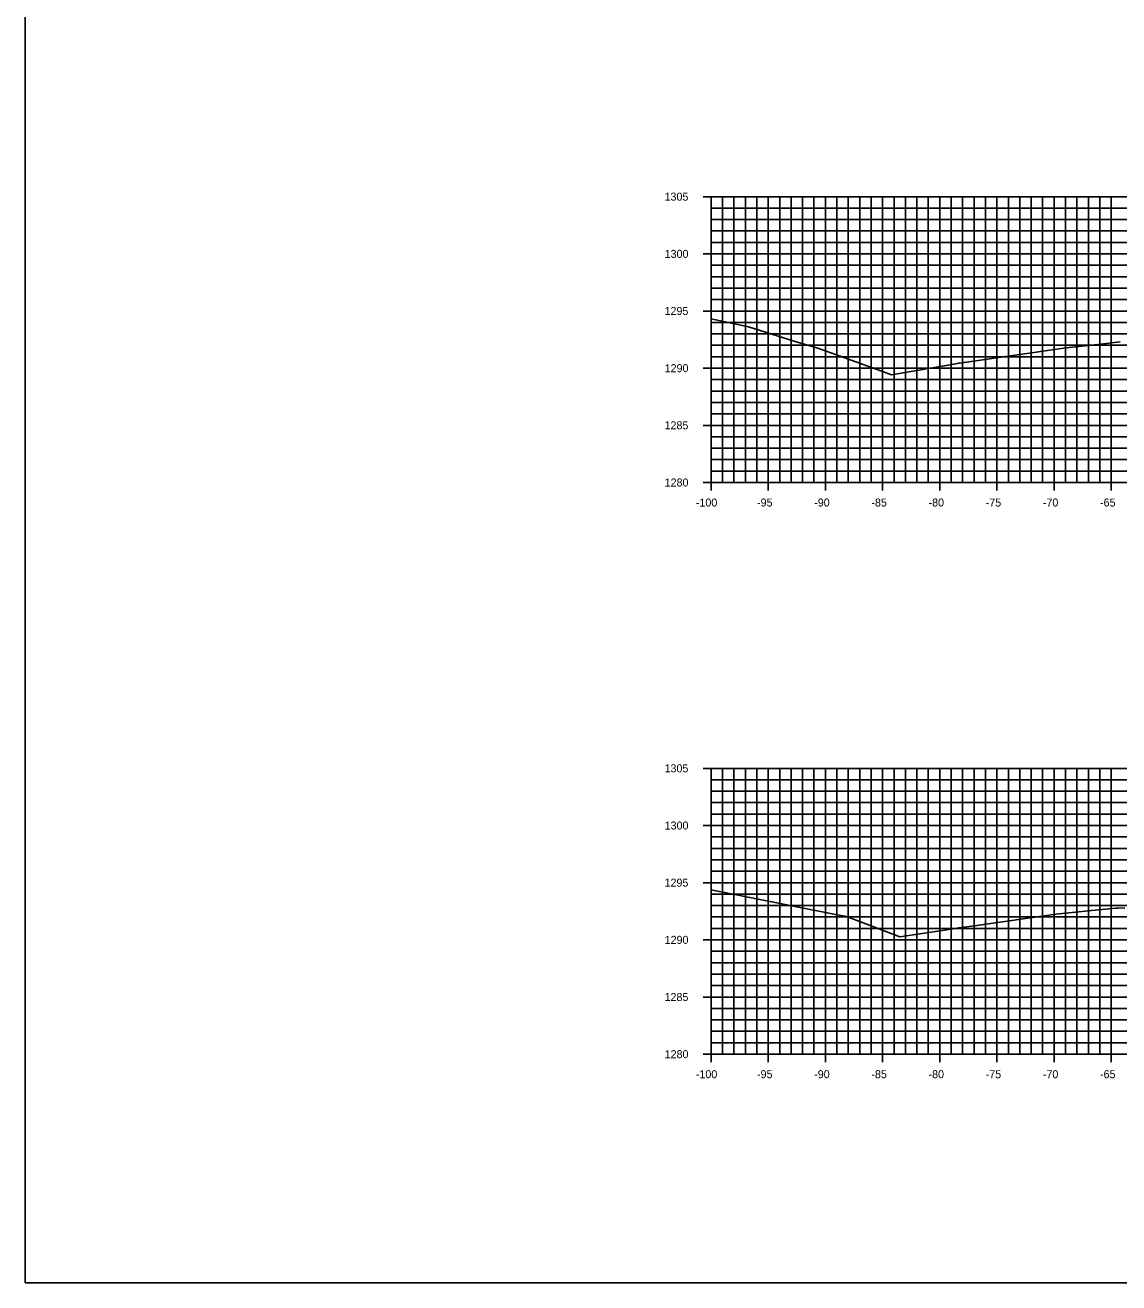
# Model space of a CAD drawing. Extents: x 674939 to 678919, y 750652 to 765176.
# Drawn here: x 678578.5 to 678674.2, y 758052.6 to 758162.6 of the extents above; entities that cross this region are included whole.
import ezdxf

# ---------------------------------------------------------------- set-up
doc = ezdxf.new("R2010")
doc.units = 0
for name, color, linetype in [('Level 10', 7, 'Continuous'), ('Level 20', 7, 'Continuous'), ('Level 4', 7, 'Continuous'), ('Level 8', 7, 'Continuous'), ('Level 9', 7, 'Continuous')]:
    doc.layers.add(name, color=color, linetype=linetype)

msp = doc.modelspace()

# ---------------------------------------------------------------- linework, layer by layer
at = {"layer": 'Level 10'}
for points in [[(678638.53, 758136.86), (678641.79, 758136.18), (678645.89, 758134.89), (678647.88, 758134.31), (678649.81, 758133.61), (678653.6, 758132.23), (678654.31, 758131.97), (678659.93, 758132.94), (678660.16, 758132.98), (678660.26, 758133), (678669.58, 758134.34), (678672.62, 758134.65), (678674.31, 758134.86)], [(678638.53, 758086.91), (678649.26, 758084.81), (678650.36, 758084.6), (678650.52, 758084.54), (678650.84, 758084.43), (678655.03, 758082.81), (678658.94, 758083.41), (678659.69, 758083.52), (678660.21, 758083.59), (678661.56, 758083.78), (678668.69, 758084.8), (678670.69, 758085.01), (678671.81, 758085.12), (678673.95, 758085.31), (678673.99, 758085.31), (678674.14, 758085.32), (678674.71, 758085.36)]]:
    msp.add_lwpolyline(points, dxfattribs=at)
at = {"layer": 'Level 20'}
for p, q in [((678638.53, 758147.55), (678838.53, 758147.55)), ((678638.53, 758122.55), (678638.53, 758147.55)), ((678639.53, 758122.55), (678639.53, 758147.55)), ((678640.53, 758122.55), (678640.53, 758147.55)), ((678641.53, 758122.55), (678641.53, 758147.55)), ((678642.53, 758122.55), (678642.53, 758147.55)), ((678643.53, 758122.55), (678643.53, 758147.55)), ((678644.53, 758122.55), (678644.53, 758147.55)), ((678645.53, 758122.55), (678645.53, 758147.55)), ((678646.53, 758122.55), (678646.53, 758147.55)), ((678647.53, 758122.55), (678647.53, 758147.55)), ((678648.53, 758122.55), (678648.53, 758147.55)), ((678649.53, 758122.55), (678649.53, 758147.55)), ((678650.53, 758122.55), (678650.53, 758147.55)), ((678651.53, 758122.55), (678651.53, 758147.55)), ((678652.53, 758122.55), (678652.53, 758147.55)), ((678653.53, 758122.55), (678653.53, 758147.55)), ((678654.53, 758122.55), (678654.53, 758147.55)), ((678655.53, 758122.55), (678655.53, 758147.55)), ((678656.53, 758122.55), (678656.53, 758147.55)), ((678657.53, 758122.55), (678657.53, 758147.55)), ((678658.53, 758122.55), (678658.53, 758147.55)), ((678659.53, 758122.55), (678659.53, 758147.55)), ((678660.53, 758122.55), (678660.53, 758147.55)), ((678661.53, 758122.55), (678661.53, 758147.55)), ((678662.53, 758122.55), (678662.53, 758147.55)), ((678663.53, 758122.55), (678663.53, 758147.55)), ((678664.53, 758122.55), (678664.53, 758147.55)), ((678665.53, 758122.55), (678665.53, 758147.55)), ((678666.53, 758122.55), (678666.53, 758147.55)), ((678667.53, 758122.55), (678667.53, 758147.55)), ((678668.53, 758122.55), (678668.53, 758147.55)), ((678669.53, 758122.55), (678669.53, 758147.55)), ((678670.53, 758122.55), (678670.53, 758147.55)), ((678671.53, 758122.55), (678671.53, 758147.55)), ((678672.53, 758122.55), (678672.53, 758147.55)), ((678673.53, 758122.55), (678673.53, 758147.55)), ((678638.53, 758146.55), (678838.53, 758146.55)), ((678638.53, 758145.55), (678838.53, 758145.55)), ((678638.53, 758144.55), (678838.53, 758144.55)), ((678638.53, 758143.55), (678838.53, 758143.55)), ((678638.53, 758142.55), (678838.53, 758142.55)), ((678638.53, 758141.55), (678838.53, 758141.55)), ((678638.53, 758140.55), (678838.53, 758140.55)), ((678638.53, 758139.55), (678838.53, 758139.55)), ((678638.53, 758138.55), (678838.53, 758138.55)), ((678638.53, 758137.55), (678838.53, 758137.55)), ((678638.53, 758136.55), (678838.53, 758136.55)), ((678638.53, 758135.55), (678838.53, 758135.55)), ((678638.53, 758134.55), (678838.53, 758134.55)), ((678638.53, 758133.55), (678838.53, 758133.55)), ((678638.53, 758132.55), (678838.53, 758132.55)), ((678638.53, 758131.55), (678838.53, 758131.55)), ((678638.53, 758130.55), (678838.53, 758130.55)), ((678638.53, 758129.55), (678838.53, 758129.55)), ((678638.53, 758128.55), (678838.53, 758128.55)), ((678638.53, 758127.55), (678838.53, 758127.55)), ((678638.53, 758126.55), (678838.53, 758126.55)), ((678638.53, 758125.55), (678838.53, 758125.55)), ((678638.53, 758124.55), (678838.53, 758124.55)), ((678638.53, 758123.55), (678838.53, 758123.55)), ((678638.53, 758122.55), (678838.53, 758122.55)), ((678638.53, 758097.55), (678838.53, 758097.55)), ((678638.53, 758072.55), (678638.53, 758097.55)), ((678639.53, 758072.55), (678639.53, 758097.55)), ((678640.53, 758072.55), (678640.53, 758097.55)), ((678641.53, 758072.55), (678641.53, 758097.55)), ((678642.53, 758072.55), (678642.53, 758097.55)), ((678643.53, 758072.55), (678643.53, 758097.55)), ((678644.53, 758072.55), (678644.53, 758097.55)), ((678645.53, 758072.55), (678645.53, 758097.55)), ((678646.53, 758072.55), (678646.53, 758097.55)), ((678647.53, 758072.55), (678647.53, 758097.55)), ((678648.53, 758072.55), (678648.53, 758097.55)), ((678649.53, 758072.55), (678649.53, 758097.55)), ((678650.53, 758072.55), (678650.53, 758097.55)), ((678651.53, 758072.55), (678651.53, 758097.55)), ((678652.53, 758072.55), (678652.53, 758097.55)), ((678653.53, 758072.55), (678653.53, 758097.55)), ((678654.53, 758072.55), (678654.53, 758097.55)), ((678655.53, 758072.55), (678655.53, 758097.55)), ((678656.53, 758072.55), (678656.53, 758097.55)), ((678657.53, 758072.55), (678657.53, 758097.55)), ((678658.53, 758072.55), (678658.53, 758097.55)), ((678659.53, 758072.55), (678659.53, 758097.55)), ((678660.53, 758072.55), (678660.53, 758097.55)), ((678661.53, 758072.55), (678661.53, 758097.55)), ((678662.53, 758072.55), (678662.53, 758097.55)), ((678663.53, 758072.55), (678663.53, 758097.55)), ((678664.53, 758072.55), (678664.53, 758097.55)), ((678665.53, 758072.55), (678665.53, 758097.55)), ((678666.53, 758072.55), (678666.53, 758097.55)), ((678667.53, 758072.55), (678667.53, 758097.55)), ((678668.53, 758072.55), (678668.53, 758097.55)), ((678669.53, 758072.55), (678669.53, 758097.55)), ((678670.53, 758072.55), (678670.53, 758097.55)), ((678671.53, 758072.55), (678671.53, 758097.55)), ((678672.53, 758072.55), (678672.53, 758097.55)), ((678673.53, 758072.55), (678673.53, 758097.55)), ((678638.53, 758096.55), (678838.53, 758096.55)), ((678638.53, 758095.55), (678838.53, 758095.55)), ((678638.53, 758094.55), (678838.53, 758094.55)), ((678638.53, 758093.55), (678838.53, 758093.55)), ((678638.53, 758092.55), (678838.53, 758092.55)), ((678638.53, 758091.55), (678838.53, 758091.55)), ((678638.53, 758090.55), (678838.53, 758090.55)), ((678638.53, 758089.55), (678838.53, 758089.55)), ((678638.53, 758088.55), (678838.53, 758088.55)), ((678638.53, 758087.55), (678838.53, 758087.55)), ((678638.53, 758086.55), (678838.53, 758086.55)), ((678638.53, 758085.55), (678838.53, 758085.55)), ((678638.53, 758084.55), (678838.53, 758084.55)), ((678638.53, 758083.55), (678838.53, 758083.55)), ((678638.53, 758082.55), (678838.53, 758082.55)), ((678638.53, 758081.55), (678838.53, 758081.55)), ((678638.53, 758080.55), (678838.53, 758080.55)), ((678638.53, 758079.55), (678838.53, 758079.55)), ((678638.53, 758078.55), (678838.53, 758078.55)), ((678638.53, 758077.55), (678838.53, 758077.55)), ((678638.53, 758076.55), (678838.53, 758076.55)), ((678638.53, 758075.55), (678838.53, 758075.55)), ((678638.53, 758074.55), (678838.53, 758074.55)), ((678638.53, 758073.55), (678838.53, 758073.55)), ((678638.53, 758072.55), (678838.53, 758072.55))]:
    msp.add_line(p, q, dxfattribs=at)
at = {"layer": 'Level 4'}
msp.add_lwpolyline([(678578.53, 758052.55), (678918.53, 758052.55), (678918.53, 758272.55), (678578.53, 758272.55)], close=True, dxfattribs=at)
at = {"layer": 'Level 8'}
for p, q in [((678637.83, 758147.55), (678639.23, 758147.55)), ((678638.53, 758122.55), (678638.53, 758147.55)), ((678638.53, 758146.55), (678638.88, 758146.55)), ((678638.53, 758145.55), (678638.88, 758145.55)), ((678638.53, 758144.55), (678638.88, 758144.55)), ((678638.53, 758143.55), (678638.88, 758143.55)), ((678637.83, 758142.55), (678639.23, 758142.55)), ((678638.53, 758141.55), (678638.88, 758141.55)), ((678638.53, 758140.55), (678638.88, 758140.55)), ((678638.53, 758139.55), (678638.88, 758139.55)), ((678638.53, 758138.55), (678638.88, 758138.55)), ((678637.83, 758137.55), (678639.23, 758137.55)), ((678638.53, 758136.55), (678638.88, 758136.55)), ((678638.53, 758135.55), (678638.88, 758135.55)), ((678638.53, 758134.55), (678638.88, 758134.55)), ((678638.53, 758133.55), (678638.88, 758133.55)), ((678637.83, 758132.55), (678639.23, 758132.55)), ((678638.53, 758131.55), (678638.88, 758131.55)), ((678638.53, 758130.55), (678638.88, 758130.55)), ((678638.53, 758129.55), (678638.88, 758129.55)), ((678638.53, 758128.55), (678638.88, 758128.55)), ((678637.83, 758127.55), (678639.23, 758127.55)), ((678638.53, 758126.55), (678638.88, 758126.55)), ((678638.53, 758125.55), (678638.88, 758125.55)), ((678638.53, 758124.55), (678638.88, 758124.55)), ((678638.53, 758123.55), (678638.88, 758123.55)), ((678637.83, 758122.55), (678639.23, 758122.55)), ((678638.53, 758121.85), (678638.53, 758123.25)), ((678638.53, 758122.55), (678838.53, 758122.55)), ((678643.53, 758121.85), (678643.53, 758123.25)), ((678648.53, 758121.85), (678648.53, 758123.25)), ((678653.53, 758121.85), (678653.53, 758123.25)), ((678658.53, 758121.85), (678658.53, 758123.25)), ((678663.53, 758121.85), (678663.53, 758123.25)), ((678668.53, 758121.85), (678668.53, 758123.25)), ((678673.53, 758121.85), (678673.53, 758123.25)), ((678637.83, 758097.55), (678639.23, 758097.55)), ((678638.53, 758072.55), (678638.53, 758097.55)), ((678638.53, 758096.55), (678638.88, 758096.55)), ((678638.53, 758095.55), (678638.88, 758095.55)), ((678638.53, 758094.55), (678638.88, 758094.55)), ((678637.83, 758092.55), (678639.23, 758092.55)), ((678638.53, 758093.55), (678638.88, 758093.55)), ((678638.53, 758091.55), (678638.88, 758091.55)), ((678638.53, 758090.55), (678638.88, 758090.55)), ((678638.53, 758089.55), (678638.88, 758089.55)), ((678638.53, 758088.55), (678638.88, 758088.55)), ((678637.83, 758087.55), (678639.23, 758087.55)), ((678638.53, 758086.55), (678638.88, 758086.55)), ((678638.53, 758085.55), (678638.88, 758085.55)), ((678638.53, 758084.55), (678638.88, 758084.55)), ((678638.53, 758083.55), (678638.88, 758083.55)), ((678637.83, 758082.55), (678639.23, 758082.55)), ((678638.53, 758081.55), (678638.88, 758081.55)), ((678638.53, 758080.55), (678638.88, 758080.55)), ((678638.53, 758079.55), (678638.88, 758079.55)), ((678638.53, 758078.55), (678638.88, 758078.55)), ((678637.83, 758077.55), (678639.23, 758077.55)), ((678638.53, 758076.55), (678638.88, 758076.55)), ((678638.53, 758075.55), (678638.88, 758075.55)), ((678638.53, 758074.55), (678638.88, 758074.55)), ((678638.53, 758073.55), (678638.88, 758073.55)), ((678638.53, 758071.85), (678638.53, 758073.25)), ((678643.53, 758071.85), (678643.53, 758073.25)), ((678648.53, 758071.85), (678648.53, 758073.25)), ((678653.53, 758071.85), (678653.53, 758073.25)), ((678658.53, 758071.85), (678658.53, 758073.25)), ((678663.53, 758071.85), (678663.53, 758073.25)), ((678668.53, 758071.85), (678668.53, 758073.25)), ((678673.53, 758071.85), (678673.53, 758073.25)), ((678637.83, 758072.55), (678639.23, 758072.55)), ((678638.53, 758072.55), (678838.53, 758072.55))]:
    msp.add_line(p, q, dxfattribs=at)

# ---------------------------------------------------------------- texts
at = {"layer": 'Level 9'}
for s, p in [('1305', (678634.46, 758147.2)), ('1300', (678634.47, 758142.2)), ('1295', (678634.46, 758137.2)), ('1290', (678634.47, 758132.2)), ('1285', (678634.46, 758127.2)), ('1280', (678634.47, 758122.2)), ('-100', (678637.2, 758120.45)), ('-95', (678642.55, 758120.45)), ('-90', (678647.55, 758120.45)), ('-85', (678652.55, 758120.45)), ('-80', (678657.55, 758120.45)), ('-75', (678662.55, 758120.45)), ('-70', (678667.55, 758120.45)), ('-65', (678672.55, 758120.45)), ('1305', (678634.46, 758097.2)), ('1300', (678634.47, 758092.2)), ('1295', (678634.46, 758087.2)), ('1290', (678634.47, 758082.2)), ('1285', (678634.46, 758077.2)), ('1280', (678634.47, 758072.2)), ('-100', (678637.2, 758070.45)), ('-95', (678642.55, 758070.45)), ('-90', (678647.55, 758070.45)), ('-85', (678652.55, 758070.45)), ('-80', (678657.55, 758070.45)), ('-75', (678662.55, 758070.45)), ('-70', (678667.55, 758070.45)), ('-65', (678672.55, 758070.45))]:
    msp.add_text(s, height=0.7, dxfattribs=at).set_placement(p)

doc.saveas('drawing.dxf')
